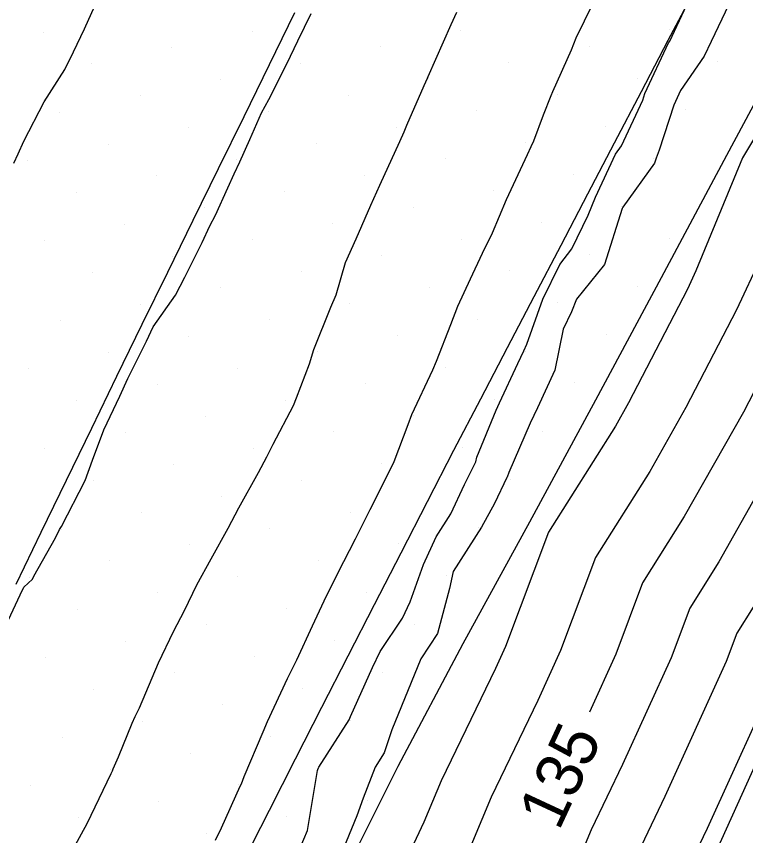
# Model space of a CAD drawing. Extents: x 2354170 to 2357230, y 866100 to 868290.
# Drawn here: x 2355336.18 to 2355367.7, y 866242.68 to 866278.11 of the extents above; entities that cross this region are included whole.
import ezdxf

# ---------------------------------------------------------------- set-up
doc = ezdxf.new("R2010")
doc.units = 0
for name, color, linetype in [('Default', 7, 'Continuous'), ('DTM Contours Major', 7, 'Continuous'), ('DTM Contours Major Text', 7, 'Continuous'), ('DTM Contours Minor', 7, 'Continuous'), ('Exist DTM Breakline', 7, 'Continuous'), ('Exist DTM Scan Elevation Point', 7, 'Continuous'), ('Exist Roads EOP', 7, 'Continuous')]:
    doc.layers.add(name, color=color, linetype=linetype)

msp = doc.modelspace()

# ---------------------------------------------------------------- linework, layer by layer
at = {"layer": 'Default'}
for points in [[(2355372.703, 866282.414), (2355370.477, 866276.829), (2355367.564, 866271.983), (2355365.553, 866267.103), (2355365.186, 866266.314), (2355362.639, 866261.396), (2355362.071, 866260.388), (2355359.176, 866255.796), (2355357.318, 866250.849), (2355356.89, 866249.903), (2355354.549, 866245.053), (2355353.798, 866243.253), (2355351.62, 866238.622), (2355349.45, 866234.095), (2355347.297, 866229.598), (2355346.657, 866228.312), (2355344.394, 866223.606), (2355343.507, 866221.542), (2355341.397, 866217.094), (2355339.299, 866212.753), (2355337.464, 866208.514), (2355336.747, 866206.664), (2355334.663, 866202.232)], [(2355377.631, 866281.887), (2355375.525, 866277.598), (2355374.162, 866274.18), (2355372.379, 866271.215), (2355371.149, 866268.228), (2355369.42, 866264.507), (2355367.602, 866260.997), (2355365.051, 866256.472), (2355363.248, 866253.611), (2355362.091, 866250.529), (2355360.949, 866248.011)], [(2355380.044, 866281.518), (2355376.936, 866275.19), (2355376.005, 866272.856), (2355374.787, 866270.83), (2355373.947, 866268.79), (2355371.537, 866263.604), (2355370.084, 866260.797), (2355366.542, 866254.513), (2355365.284, 866252.519), (2355364.477, 866250.37), (2355362.381, 866245.748), (2355361.023, 866242.933), (2355357.68, 866234.925), (2355356.871, 866233.205), (2355356.065, 866231.522), (2355355.265, 866229.852), (2355352.643, 866224.577), (2355351.396, 866221.986), (2355347.866, 866213.765), (2355347.178, 866212.315), (2355346.493, 866210.899), (2355345.895, 866209.516), (2355343.476, 866203.275)], [(2355382.456, 866281.15), (2355378.347, 866272.782), (2355377.848, 866271.531), (2355377.195, 866270.446), (2355376.745, 866269.353), (2355373.654, 866262.7), (2355372.565, 866260.598), (2355368.032, 866252.555), (2355367.32, 866251.426), (2355366.864, 866250.21), (2355364.212, 866244.363), (2355363.181, 866242.227), (2355358.974, 866232.149), (2355358.621, 866231.399), (2355358.27, 866230.665), (2355357.921, 866229.936), (2355354.638, 866223.332), (2355353.73, 866221.446), (2355349.319, 866211.173), (2355349.105, 866210.721), (2355348.892, 866210.281), (2355348.705, 866209.85), (2355345.719, 866202.145)], [(2355384.869, 866280.782), (2355379.757, 866270.375), (2355379.691, 866270.207), (2355379.603, 866270.061), (2355379.543, 866269.915), (2355375.771, 866261.796), (2355375.047, 866260.398), (2355369.523, 866250.597), (2355369.357, 866250.334), (2355369.25, 866250.05), (2355366.043, 866242.978), (2355365.339, 866241.52), (2355360.929, 866230.955), (2355360.64, 866230.002), (2355360.393, 866229.584), (2355359.976, 866228.811), (2355356.633, 866222.087), (2355356.065, 866220.906), (2355352.44, 866212.466), (2355351.26, 866210.001), (2355351.051, 866208.925), (2355349.975, 866206.21), (2355347.962, 866201.015)], [(2355374.114, 866280.006), (2355372.32, 866275.505), (2355369.972, 866271.599), (2355368.351, 866267.665), (2355367.303, 866265.411), (2355365.12, 866261.196), (2355363.561, 866258.43), (2355361.212, 866254.704), (2355359.705, 866250.689), (2355358.72, 866248.518), (2355356.707, 866244.347), (2355355.092, 866240.477), (2355353.37, 866236.816), (2355351.655, 866233.237), (2355349.953, 866229.683), (2355348.653, 866227.067), (2355346.728, 866223.066), (2355344.96, 866218.95), (2355343.324, 866215.501), (2355341.697, 866212.135), (2355340.274, 866208.848), (2355338.99, 866205.534), (2355337.259, 866201.854), (2355334.972, 866197.269)], [(2355344.79, 866242.478), (2355345.044, 866243.012), (2355345.861, 866244.809), (2355345.906, 866244.921), (2355346.032, 866245.232), (2355346.843, 866247.17), (2355347.037, 866247.606), (2355347.894, 866249.471), (2355348.298, 866250.273), (2355348.976, 866251.753), (2355349.487, 866252.837), (2355350.079, 866254.021), (2355350.84, 866255.507), (2355351.216, 866256.267), (2355351.468, 866256.786), (2355352.327, 866258.467), (2355352.51, 866258.856), (2355353.11, 866260.462), (2355353.281, 866260.895), (2355354.185, 866262.814), (2355354.341, 866263.192), (2355354.966, 866264.777), (2355355.266, 866265.578), (2355355.805, 866266.752), (2355356.334, 866267.869), (2355356.766, 866268.752), (2355357.369, 866270.181), (2355358.278, 866272.134), (2355358.436, 866272.473), (2355358.545, 866272.722), (2355358.966, 866273.845), (2355359.297, 866274.68), (2355359.374, 866274.851), (2355360.172, 866276.662), (2355360.382, 866277.181), (2355361.099, 866278.655)], [(2355338.334, 866241.545), (2355339.24, 866243.206), (2355340.277, 866245.368), (2355340.332, 866245.482), (2355340.37, 866245.568), (2355340.598, 866246.08), (2355341.193, 866247.54), (2355341.322, 866247.825), (2355341.503, 866248.206), (2355342.33, 866250.155), (2355342.968, 866251.509), (2355343.444, 866252.416), (2355343.989, 866253.521), (2355344.602, 866254.647), (2355345.334, 866255.968), (2355345.796, 866256.855), (2355346.646, 866258.385), (2355347.006, 866259.052), (2355347.283, 866259.604), (2355348.164, 866261.283), (2355348.288, 866261.613), (2355348.847, 866263.08), (2355349.042, 866263.7), (2355349.776, 866265.524), (2355350, 866266.064), (2355350.401, 866267.456), (2355350.872, 866268.485), (2355351.509, 866269.939), (2355351.893, 866270.807), (2355352.752, 866272.693), (2355352.94, 866273.112), (2355353.058, 866273.409), (2355353.811, 866275.114), (2355353.955, 866275.438), (2355353.985, 866275.501), (2355354.981, 866277.757), (2355355.22, 866278.294)], [(2355366.974, 866278.621), (2355366.208, 866277.023), (2355365.911, 866276.388), (2355364.891, 866274.895), (2355364.596, 866274.266), (2355363.958, 866272.327), (2355363.841, 866271.977), (2355363.767, 866271.757), (2355362.388, 866269.859), (2355362.362, 866269.799), (2355361.6, 866267.383), (2355360.386, 866265.881), (2355360.17, 866265.331), (2355359.818, 866264.575), (2355359.457, 866262.805), (2355358.705, 866261.182), (2355358.394, 866260.511), (2355357.472, 866258.375), (2355357.391, 866258.177), (2355357.386, 866258.158), (2355356.845, 866257.045), (2355356.279, 866256.012), (2355355.062, 866254.101), (2355354.904, 866253.364), (2355354.385, 866251.421), (2355353.657, 866250.326), (2355352.417, 866247.246), (2355352.074, 866246.252), (2355351.695, 866245.641), (2355351.174, 866244.304), (2355350.898, 866243.526), (2355349.976, 866241.288)], [(2355335.642, 866251.583), (2355336.353, 866253.095), (2355336.5, 866253.418), (2355336.878, 866253.762), (2355336.944, 866253.891), (2355337.873, 866255.555), (2355338.046, 866255.923), (2355338.137, 866256.049), (2355339.151, 866258.03), (2355339.478, 866258.91), (2355339.968, 866260.23), (2355340.656, 866261.681), (2355341.004, 866262.452), (2355341.807, 866264.059), (2355342.093, 866264.677), (2355343.053, 866266.052), (2355343.458, 866266.826), (2355344.216, 866268.328), (2355344.543, 866269.054), (2355344.782, 866269.516), (2355345.324, 866270.696), (2355345.589, 866271.301), (2355345.835, 866271.817), (2355346.272, 866272.781), (2355346.783, 866273.935), (2355347.087, 866274.507), (2355347.868, 866276.055), (2355348.351, 866277.048), (2355348.917, 866278.225)]]:
    msp.add_lwpolyline(points, dxfattribs=at)
at = {"layer": 'DTM Contours Major'}
msp.add_lwpolyline([(2355377.631, 866281.887), (2355375.525, 866277.598), (2355374.162, 866274.18), (2355372.379, 866271.215), (2355371.149, 866268.228), (2355369.42, 866264.507), (2355367.602, 866260.997), (2355365.051, 866256.472), (2355363.248, 866253.611), (2355362.091, 866250.529), (2355360.949, 866248.011)], dxfattribs=at)
at = {"layer": 'DTM Contours Minor'}
for points in [[(2355385.673, 866280.659), (2355380.886, 866270.912), (2355380.463, 866270.002), (2355379.976, 866269.027), (2355376.477, 866261.495), (2355375.874, 866260.332), (2355370.15, 866250.176), (2355370.069, 866250.002), (2355370.041, 866249.937), (2355369.976, 866249.843), (2355366.653, 866242.516), (2355366.058, 866241.284), (2355362.332, 866232.358), (2355361.618, 866230.002), (2355361.007, 866228.97), (2355359.976, 866227.058), (2355357.298, 866221.672), (2355356.843, 866220.726), (2355353.939, 866213.965), (2355352.041, 866210.001), (2355351.706, 866208.271), (2355349.975, 866203.904)], [(2355336.077, 866271.755), (2355336.259, 866272.158), (2355336.511, 866272.715), (2355337.387, 866274.409), (2355338.282, 866275.812), (2355338.646, 866276.574), (2355339.132, 866277.562), (2355339.705, 866278.87)], [(2355348.291, 866241.769), (2355348.759, 866242.904), (2355349.201, 866245.491), (2355349.232, 866245.583), (2355349.258, 866245.637), (2355350.563, 866247.69), (2355350.627, 866247.832), (2355351.569, 866249.949), (2355351.903, 866250.637), (2355352.864, 866252.082), (2355353.205, 866252.789), (2355353.773, 866254.406), (2355354.333, 866255.595), (2355354.956, 866256.599), (2355355.554, 866257.859), (2355356.034, 866258.848), (2355356.086, 866259.04), (2355356.923, 866261.072), (2355357.061, 866261.392), (2355357.852, 866263.099), (2355358.114, 866263.648), (2355358.249, 866263.928), (2355358.943, 866265.883), (2355359.667, 866267.376), (2355360.19, 866268.047), (2355360.9, 866269.512), (2355361.206, 866270.294), (2355362.08, 866272.153), (2355362.335, 866272.51), (2355363.251, 866274.484), (2355363.348, 866274.778), (2355364.368, 866276.956), (2355364.418, 866277.028), (2355365.143, 866278.58)]]:
    msp.add_lwpolyline(points, dxfattribs=at)
at = {"layer": 'Exist DTM Breakline'}
for points in [[(2355365.507, 866279.272), (2355364.342, 866277.061), (2355363.183, 866274.846), (2355362.024, 866272.63), (2355360.866, 866270.415), (2355359.707, 866268.2), (2355358.55, 866265.984), (2355357.393, 866263.767), (2355356.236, 866261.551), (2355355.079, 866259.335), (2355353.936, 866257.112), (2355352.794, 866254.888), (2355351.652, 866252.664), (2355350.51, 866250.44), (2355349.374, 866248.213), (2355348.238, 866245.986), (2355347.102, 866243.759), (2355345.967, 866241.531)], [(2355336.167, 866253.553), (2355337.256, 866255.804), (2355338.347, 866258.053), (2355339.438, 866260.303), (2355340.531, 866262.551), (2355341.626, 866264.798), (2355342.724, 866267.045), (2355343.823, 866269.29), (2355344.923, 866271.535), (2355346.024, 866273.779), (2355347.123, 866276.025), (2355348.221, 866278.271)]]:
    msp.add_lwpolyline(points, dxfattribs=at)
at = {"layer": 'Exist DTM Scan Elevation Point'}
for p, q in [((2355337.356, 866277.427), (2355337.356, 866277.427)), ((2355346.37, 866277.459), (2355346.37, 866277.459)), ((2355355.383, 866277.491), (2355355.383, 866277.491)), ((2355364.397, 866277.522), (2355364.397, 866277.522)), ((2355342.905, 866276.753), (2355342.905, 866276.753)), ((2355351.919, 866276.785), (2355351.919, 866276.785)), ((2355360.933, 866276.817), (2355360.933, 866276.817)), ((2355339.441, 866276.048), (2355339.441, 866276.048)), ((2355348.455, 866276.079), (2355348.455, 866276.079)), ((2355357.468, 866276.111), (2355357.468, 866276.111)), ((2355366.482, 866276.143), (2355366.482, 866276.143)), ((2355344.99, 866275.374), (2355344.99, 866275.374)), ((2355354.004, 866275.406), (2355354.004, 866275.406)), ((2355363.018, 866275.437), (2355363.018, 866275.437)), ((2355341.526, 866274.668), (2355341.526, 866274.668)), ((2355350.539, 866274.7), (2355350.539, 866274.7)), ((2355359.553, 866274.732), (2355359.553, 866274.732)), ((2355365.103, 866274.058), (2355365.103, 866274.058)), ((2355338.061, 866273.963), (2355338.061, 866273.963)), ((2355347.075, 866273.994), (2355347.075, 866273.994)), ((2355356.089, 866274.026), (2355356.089, 866274.026)), ((2355361.638, 866273.352), (2355361.638, 866273.352)), ((2355343.611, 866273.289), (2355343.611, 866273.289)), ((2355352.624, 866273.321), (2355352.624, 866273.321)), ((2355358.174, 866272.647), (2355358.174, 866272.647)), ((2355340.146, 866272.583), (2355340.146, 866272.583)), ((2355349.16, 866272.615), (2355349.16, 866272.615)), ((2355354.709, 866271.941), (2355354.709, 866271.941)), ((2355363.723, 866271.973), (2355363.723, 866271.973)), ((2355336.682, 866271.878), (2355336.682, 866271.878)), ((2355345.696, 866271.909), (2355345.696, 866271.909)), ((2355351.245, 866271.236), (2355351.245, 866271.236)), ((2355360.259, 866271.267), (2355360.259, 866271.267)), ((2355342.231, 866271.204), (2355342.231, 866271.204)), ((2355338.767, 866270.498), (2355338.767, 866270.498)), ((2355347.781, 866270.53), (2355347.781, 866270.53)), ((2355356.794, 866270.562), (2355356.794, 866270.562)), ((2355344.316, 866269.824), (2355344.316, 866269.824)), ((2355353.33, 866269.856), (2355353.33, 866269.856)), ((2355362.344, 866269.888), (2355362.344, 866269.888)), ((2355340.852, 866269.119), (2355340.852, 866269.119)), ((2355349.866, 866269.151), (2355349.866, 866269.151)), ((2355358.879, 866269.182), (2355358.879, 866269.182)), ((2355337.387, 866268.413), (2355337.387, 866268.413)), ((2355346.401, 866268.445), (2355346.401, 866268.445)), ((2355355.415, 866268.477), (2355355.415, 866268.477)), ((2355364.429, 866268.508), (2355364.429, 866268.508)), ((2355342.937, 866267.739), (2355342.937, 866267.739)), ((2355351.951, 866267.771), (2355351.951, 866267.771)), ((2355360.964, 866267.803), (2355360.964, 866267.803)), ((2355339.472, 866267.034), (2355339.472, 866267.034)), ((2355348.486, 866267.066), (2355348.486, 866267.066)), ((2355357.5, 866267.097), (2355357.5, 866267.097)), ((2355345.022, 866266.36), (2355345.022, 866266.36)), ((2355354.036, 866266.392), (2355354.036, 866266.392)), ((2355363.049, 866266.423), (2355363.049, 866266.423)), ((2355341.557, 866265.654), (2355341.557, 866265.654)), ((2355350.571, 866265.686), (2355350.571, 866265.686)), ((2355359.585, 866265.718), (2355359.585, 866265.718)), ((2355338.093, 866264.949), (2355338.093, 866264.949)), ((2355347.107, 866264.981), (2355347.107, 866264.981)), ((2355356.121, 866265.012), (2355356.121, 866265.012)), ((2355343.642, 866264.275), (2355343.642, 866264.275)), ((2355352.656, 866264.307), (2355352.656, 866264.307)), ((2355361.67, 866264.338), (2355361.67, 866264.338)), ((2355340.178, 866263.569), (2355340.178, 866263.569)), ((2355349.192, 866263.601), (2355349.192, 866263.601)), ((2355358.206, 866263.633), (2355358.206, 866263.633)), ((2355336.713, 866262.864), (2355336.713, 866262.864)), ((2355345.727, 866262.896), (2355345.727, 866262.896)), ((2355354.741, 866262.927), (2355354.741, 866262.927)), ((2355342.263, 866262.19), (2355342.263, 866262.19)), ((2355351.277, 866262.222), (2355351.277, 866262.222)), ((2355360.291, 866262.253), (2355360.291, 866262.253)), ((2355338.798, 866261.484), (2355338.798, 866261.484)), ((2355347.812, 866261.516), (2355347.812, 866261.516)), ((2355356.826, 866261.548), (2355356.826, 866261.548)), ((2355344.348, 866260.811), (2355344.348, 866260.811)), ((2355353.362, 866260.842), (2355353.362, 866260.842)), ((2355340.883, 866260.105), (2355340.883, 866260.105)), ((2355349.897, 866260.137), (2355349.897, 866260.137)), ((2355358.911, 866260.168), (2355358.911, 866260.168)), ((2355337.419, 866259.4), (2355337.419, 866259.4)), ((2355346.433, 866259.431), (2355346.433, 866259.431)), ((2355355.447, 866259.463), (2355355.447, 866259.463)), ((2355342.968, 866258.726), (2355342.968, 866258.726)), ((2355351.982, 866258.757), (2355351.982, 866258.757)), ((2355339.504, 866258.02), (2355339.504, 866258.02)), ((2355348.518, 866258.052), (2355348.518, 866258.052)), ((2355357.532, 866258.083), (2355357.532, 866258.083)), ((2355345.053, 866257.346), (2355345.053, 866257.346)), ((2355341.589, 866256.641), (2355341.589, 866256.641)), ((2355350.603, 866256.672), (2355350.603, 866256.672)), ((2355356.152, 866255.998), (2355356.152, 866255.998)), ((2355338.125, 866255.935), (2355338.125, 866255.935)), ((2355347.138, 866255.967), (2355347.138, 866255.967)), ((2355352.688, 866255.293), (2355352.688, 866255.293)), ((2355343.674, 866255.261), (2355343.674, 866255.261)), ((2355340.21, 866254.556), (2355340.21, 866254.556)), ((2355349.223, 866254.587), (2355349.223, 866254.587)), ((2355336.745, 866253.85), (2355336.745, 866253.85)), ((2355345.759, 866253.882), (2355345.759, 866253.882)), ((2355354.773, 866253.913), (2355354.773, 866253.913)), ((2355342.295, 866253.176), (2355342.295, 866253.176)), ((2355351.308, 866253.208), (2355351.308, 866253.208)), ((2355338.83, 866252.471), (2355338.83, 866252.471)), ((2355347.844, 866252.502), (2355347.844, 866252.502)), ((2355344.38, 866251.797), (2355344.38, 866251.797)), ((2355353.393, 866251.828), (2355353.393, 866251.828)), ((2355340.915, 866251.091), (2355340.915, 866251.091)), ((2355349.929, 866251.123), (2355349.929, 866251.123)), ((2355337.451, 866250.386), (2355337.451, 866250.386)), ((2355346.465, 866250.417), (2355346.465, 866250.417)), ((2355343, 866249.712), (2355343, 866249.712)), ((2355352.014, 866249.743), (2355352.014, 866249.743)), ((2355339.536, 866249.006), (2355339.536, 866249.006)), ((2355348.55, 866249.038), (2355348.55, 866249.038)), ((2355345.085, 866248.332), (2355345.085, 866248.332)), ((2355341.621, 866247.627), (2355341.621, 866247.627)), ((2355350.635, 866247.658), (2355350.635, 866247.658)), ((2355338.156, 866246.921), (2355338.156, 866246.921)), ((2355347.17, 866246.953), (2355347.17, 866246.953)), ((2355343.706, 866246.247), (2355343.706, 866246.247)), ((2355340.241, 866245.542), (2355340.241, 866245.542)), ((2355349.255, 866245.574), (2355349.255, 866245.574)), ((2355336.777, 866244.836), (2355336.777, 866244.836)), ((2355345.791, 866244.868), (2355345.791, 866244.868)), ((2355342.326, 866244.162), (2355342.326, 866244.162)), ((2355351.34, 866244.194), (2355351.34, 866244.194)), ((2355338.862, 866243.457), (2355338.862, 866243.457)), ((2355347.876, 866243.489), (2355347.876, 866243.489)), ((2355344.411, 866242.783), (2355344.411, 866242.783))]:
    msp.add_line(p, q, dxfattribs=at)
at = {"layer": 'Exist Roads EOP'}
msp.add_lwpolyline([(2355372.558, 866282.661), (2355369.709, 866277.381), (2355366.873, 866272.094), (2355364.047, 866266.801), (2355361.216, 866261.51), (2355358.356, 866256.236), (2355355.477, 866250.972), (2355352.672, 866245.668), (2355349.995, 866240.299), (2355347.368, 866234.904), (2355344.727, 866229.517), (2355342.047, 866224.149), (2355339.343, 866218.793), (2355336.627, 866213.442), (2355333.912, 866208.092)], dxfattribs=at)

# ---------------------------------------------------------------- texts
at = {"layer": 'Default'}
msp.add_text('135', height=2, rotation=65.0586, dxfattribs=at).set_placement((2355359.627, 866242.843))
at = {"layer": 'DTM Contours Major Text'}
msp.add_text('135', height=2, rotation=65.0586, dxfattribs=at).set_placement((2355359.627, 866242.843))

doc.saveas('drawing.dxf')
